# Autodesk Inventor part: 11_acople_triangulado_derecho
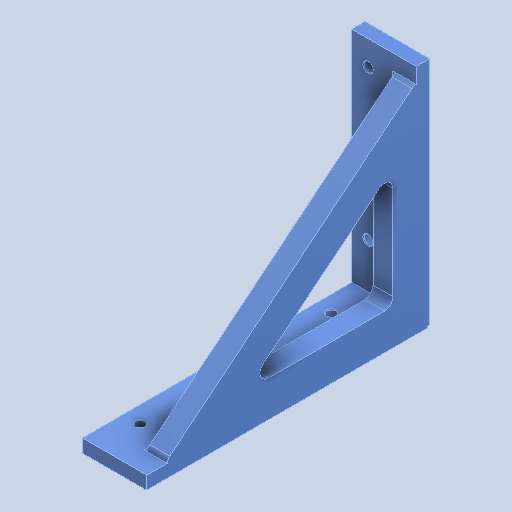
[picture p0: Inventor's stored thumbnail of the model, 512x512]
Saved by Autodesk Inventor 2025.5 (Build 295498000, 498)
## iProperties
Created: 2026-10
Part Number: 11_acople_triangulado_derecho
Material: Genérico
Document SubType Name: Modeling
Designer: Luis M
Density: 1 g/cm^3
Appearance: Valor por defecto
Author: Luis M
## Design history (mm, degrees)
feature "Base1"
node "Sólido1"
